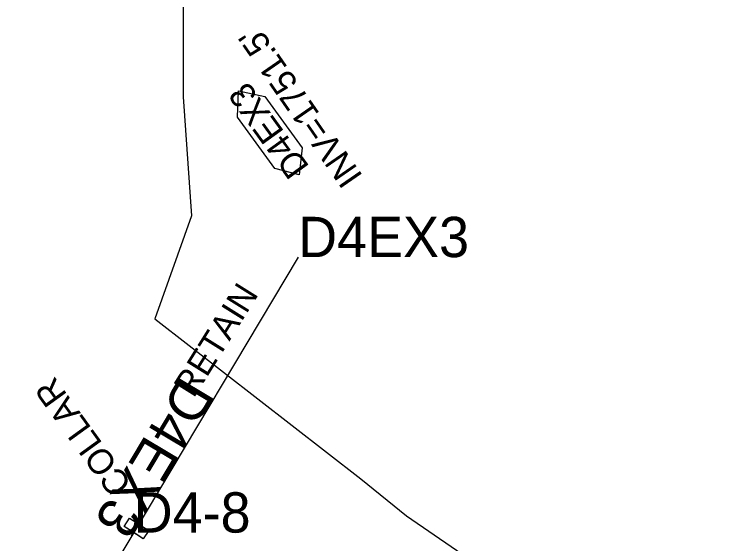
# Model space of a CAD drawing. Extents: x 465700 to 483515, y 488970 to 507540.
# Drawn here: x 475126.3 to 475267.7, y 502822.3 to 502927.4 of the extents above; entities that cross this region are included whole.
import ezdxf

# ---------------------------------------------------------------- set-up
doc = ezdxf.new("R2010")
doc.units = 0
for name, color, linetype in [('Exist Plan Preparation Watershed Blue', 7, 'Continuous'), ('Prop Drainage Structure Box Number Symbol CELL', 7, 'Continuous'), ('Prop Drainage Structure Pipe Collar CELL', 7, 'Continuous'), ('Prop Drainage Structure Pipe Collar Label', 7, 'Continuous'), ('Prop Drainage Structure Pipe CSP 18in', 7, 'Continuous'), ('Prop Drainage Structure Pipe Stub Out CELL', 7, 'Continuous'), ('Prop Drainage Structure Tops and Inverts LABEL', 7, 'Continuous'), ('Scratch_Level_8', 7, 'Continuous')]:
    doc.layers.add(name, color=color, linetype=linetype)

msp = doc.modelspace()

# ---------------------------------------------------------------- linework, layer by layer
at = {"layer": 'Exist Plan Preparation Watershed Blue'}
msp.add_lwpolyline([(475154.13, 502866.93), (475194.97, 502835.2), (475204.03, 502827.84), (475282.49, 502773.99), (475299.69, 502757.74), (475316.56, 502741.32), (475336.83, 502775.22), (475334.4, 502798.99), (475316.9, 502836.72), (475282.09, 502903.8), (475239.65, 503008.54), (475187.56, 503080.37), (475160.16, 503050.45), (475152.16, 503027.47), (475155.18, 502992.44), (475159.74, 502954.74), (475159.72, 502910.97), (475161.43, 502887.39)], close=True, dxfattribs=at)
at = {"layer": 'Prop Drainage Structure Box Number Symbol CELL'}
msp.add_lwpolyline([(475177.89, 502896.76), (475170.5, 502906.97), (475170.71, 502912.19), (475175.92, 502911.09), (475183.32, 502900.88), (475182.76, 502895.54), (475177.89, 502896.76)], dxfattribs=at)
at = {"layer": 'Prop Drainage Structure Pipe Collar CELL'}
msp.add_line((475149.93, 502824.54), (475149.93, 502824.54), dxfattribs=at)
msp.add_line((475149.93, 502824.54), (475149.93, 502824.54), dxfattribs=at)
msp.add_lwpolyline([(475148.02, 502825.76), (475149.09, 502827.43), (475152.91, 502824.97), (475151.84, 502823.31)], close=True, dxfattribs=at)
msp.add_lwpolyline([(475149.51, 502823.89), (475149.93, 502824.54), (475148.02, 502825.76), (475149.09, 502827.43), (475152.91, 502824.97), (475151.84, 502823.31), (475151.84, 502823.31), (475149.93, 502824.54)], dxfattribs=at)
at = {"layer": 'Prop Drainage Structure Pipe CSP 18in'}
msp.add_line((475149.93, 502824.54), (475126.25, 502785.19), dxfattribs=at)
at = {"layer": 'Prop Drainage Structure Pipe Stub Out CELL'}
msp.add_line((475182.54, 502879.19), (475182.54, 502879.19), dxfattribs=at)
msp.add_line((475182.54, 502879.19), (475182.54, 502879.19), dxfattribs=at)
msp.add_lwpolyline([(475182.53, 502879.18), (475182.53, 502879.2), (475182.55, 502879.2), (475182.55, 502879.18), (475182.53, 502879.18)], dxfattribs=at)
at = {"layer": 'Scratch_Level_8'}
for p, q in [((475182.54, 502879.19), (475149.93, 502824.54)), ((475149.93, 502824.54), (475126.29, 502785.35))]:
    msp.add_line(p, q, dxfattribs=at)

# ---------------------------------------------------------------- texts
at = {"layer": 'Prop Drainage Structure Box Number Symbol CELL'}
msp.add_text('D4EX3', height=5, rotation=125.9045, dxfattribs=at).set_placement((475184.91, 502897.11))
at = {"layer": 'Prop Drainage Structure Pipe Collar Label'}
for s, rotation, p in [('RETAIN', 58.0321, (475161.84, 502851.08)), ('COLLAR', 125.9074, (475149.74, 502834.09))]:
    msp.add_text(s, height=5, rotation=rotation, dxfattribs=at).set_placement(p)
at = {"layer": 'Prop Drainage Structure Pipe Stub Out CELL'}
msp.add_text('SO', height=0.0104, rotation=52.5438, dxfattribs=at).set_placement((475182.54, 502879.18))
at = {"layer": 'Prop Drainage Structure Tops and Inverts LABEL'}
msp.add_text("INV=1751.5'", height=5, rotation=124.6912, dxfattribs=at).set_placement((475195.5, 502895.24))
at = {"layer": 'Scratch_Level_8'}
for s, p in [('D4EX3', (475182.54, 502879.19)), ('D4-8', (475149.93, 502824.54))]:
    msp.add_text(s, height=8, dxfattribs=at).set_placement(p)
msp.add_text('D4EX3', height=8, rotation=239.179, dxfattribs=at).set_placement((475159.36, 502855.96))

doc.saveas('drawing.dxf')
